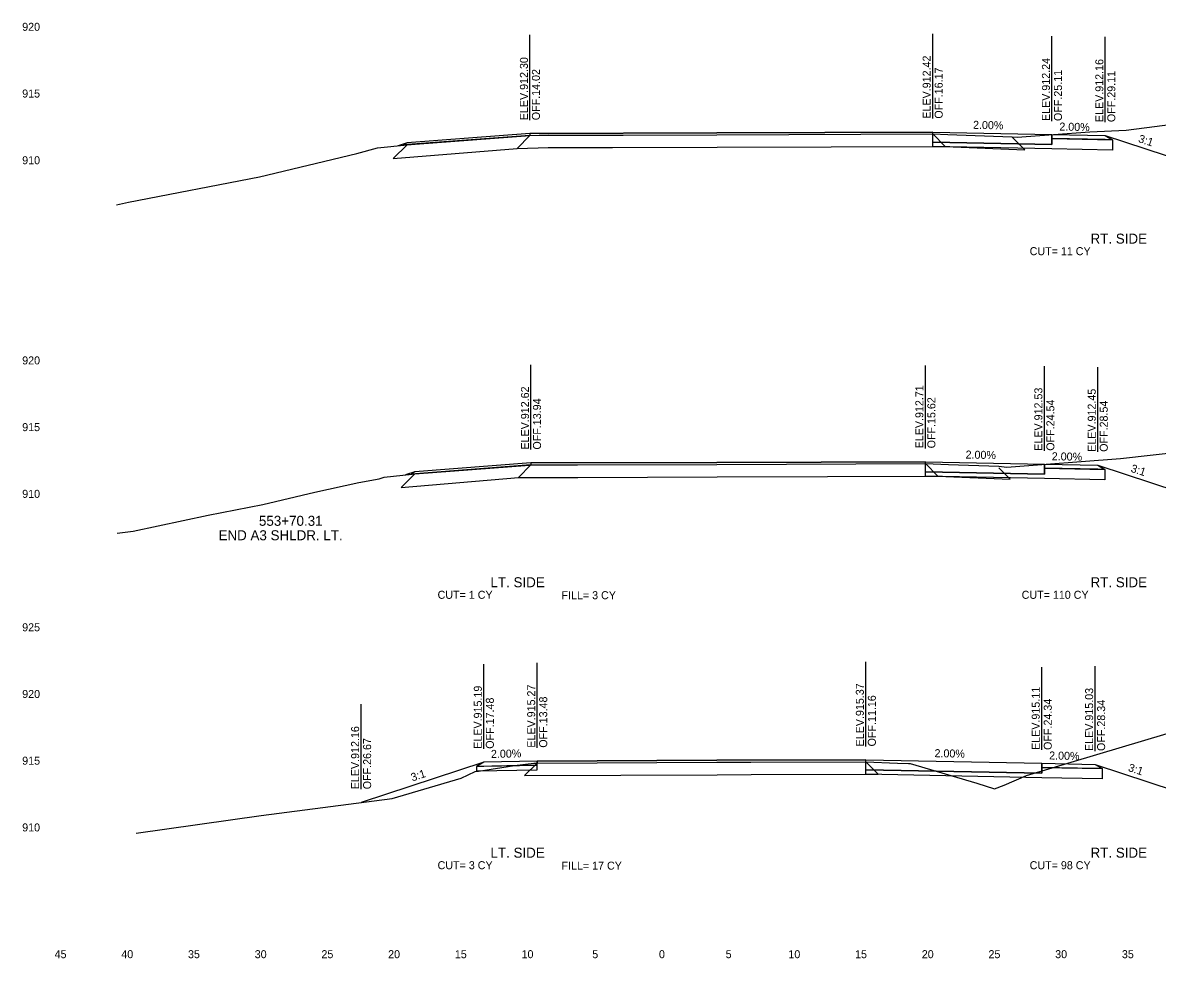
# Model space of a CAD drawing. Extents: x -4 to 359, y 0 to 1436.
# Drawn here: x 200.5 to 285.5, y 1200.5 to 1270.6 of the extents above; entities that cross this region are included whole.
import ezdxf

# ---------------------------------------------------------------- set-up
doc = ezdxf.new("R2010")
doc.units = 0
for name, color, linetype in [('XS-Existing subsurface-pavement', 7, 'Continuous'), ('XS-Existing subsurface-shoulder', 7, 'Continuous'), ('XS-Existing surface-ground', 7, 'Continuous'), ('XS-Proposed Finish Grade', 7, 'Continuous'), ('XS-Proposed subsurface-aggregate layer 1', 7, 'Continuous'), ('XS-Proposed surface-ground', 7, 'Continuous'), ('XS-Proposed surface-pavement', 7, 'Continuous'), ('XS-Proposed surface-shoulder', 7, 'Continuous'), ('XS-Text-ditch slope', 7, 'Continuous'), ('XS-Text-earthwork labels', 7, 'Continuous'), ('XS-Text-elevation', 7, 'Continuous'), ('XS-Text-offset label', 7, 'Continuous'), ('XS-Text-pavement elevation', 7, 'Continuous'), ('XS-Text-pavement slope', 7, 'Continuous'), ('XS-Text-profile report', 7, 'Continuous'), ('XS-Text-shoulder elevation', 7, 'Continuous'), ('XS-Text-shoulder slope', 7, 'Continuous'), ('XS-Text-tie elevation', 7, 'Continuous'), ('XS-Text-tie offset', 7, 'Continuous')]:
    doc.layers.add(name, color=color, linetype=linetype)

msp = doc.modelspace()

# ---------------------------------------------------------------- linework, layer by layer
at = {"layer": 'XS-Existing subsurface-pavement'}
for p, q in [((238.48, 1262.118), (237.512, 1261.15)), ((268.669, 1262.236), (269.603, 1261.301)), ((244.676, 1261.213), (252.503, 1261.241)), ((252.503, 1261.241), (269.603, 1261.301)), ((237.512, 1261.15), (239.871, 1261.224)), ((239.84, 1261.223), (244.67, 1261.213)), ((238.56, 1237.435), (237.622, 1236.498)), ((268.121, 1237.526), (269.055, 1236.592)), ((252.503, 1236.533), (269.055, 1236.592)), ((237.622, 1236.498), (242.058, 1236.496)), ((242.061, 1236.496), (252.503, 1236.533)), ((239.025, 1215.092), (238.083, 1214.151)), ((263.659, 1215.189), (264.593, 1214.254)), ((238.083, 1214.151), (252.504, 1214.212)), ((252.504, 1214.212), (255.054, 1214.223)), ((255.053, 1214.223), (264.593, 1214.254))]:
    msp.add_line(p, q, dxfattribs=at)
at = {"layer": 'XS-Existing subsurface-shoulder'}
for p, q in [((229.266, 1261.43), (228.234, 1260.398)), ((269.603, 1261.301), (275.584, 1261.054)), ((274.612, 1262.026), (275.584, 1261.054)), ((228.234, 1260.398), (237.512, 1261.15)), ((229.855, 1236.765), (228.837, 1235.748)), ((269.055, 1236.592), (274.476, 1236.364)), ((273.621, 1237.219), (274.476, 1236.364)), ((228.837, 1235.748), (237.622, 1236.498))]:
    msp.add_line(p, q, dxfattribs=at)
at = {"layer": 'XS-Existing surface-ground'}
for p, q in [((283.172, 1262.511), (291.485, 1263.596)), ((229.87, 1261.463), (238.48, 1262.118)), ((238.48, 1262.118), (239.842, 1262.161)), ((239.842, 1262.161), (244.672, 1262.151)), ((244.672, 1262.151), (252.5, 1262.178)), ((252.5, 1262.178), (268.669, 1262.236)), ((268.669, 1262.236), (269.807, 1262.195)), ((269.807, 1262.195), (274.612, 1262.026)), ((275.001, 1261.983), (280.453, 1262.398)), ((280.453, 1262.398), (283.172, 1262.511)), ((227.06, 1261.185), (229.266, 1261.43)), ((229.266, 1261.43), (229.87, 1261.463)), ((274.612, 1262.026), (275.001, 1261.983)), ((218.205, 1259.032), (225.508, 1260.772)), ((225.508, 1260.772), (227.06, 1261.185)), ((208.386, 1257.127), (218.205, 1259.032)), ((207.5, 1256.928), (208.386, 1257.127)), ((282.746, 1237.917), (310.956, 1241.132)), ((238.451, 1237.42), (238.56, 1237.435)), ((238.56, 1237.435), (242.058, 1237.434)), ((242.058, 1237.434), (252.5, 1237.471)), ((252.5, 1237.471), (268.121, 1237.526)), ((268.121, 1237.526), (269.849, 1237.464)), ((269.849, 1237.464), (273.621, 1237.332)), ((274.225, 1237.265), (282.746, 1237.917)), ((227.566, 1236.511), (229.659, 1236.737)), ((229.659, 1236.737), (229.855, 1236.765)), ((229.855, 1236.765), (238.451, 1237.42)), ((273.621, 1237.332), (274.225, 1237.265)), ((222.346, 1235.394), (225.651, 1236.113)), ((225.651, 1236.113), (227.182, 1236.394)), ((227.182, 1236.394), (227.566, 1236.511)), ((218.451, 1234.466), (222.346, 1235.394)), ((214.367, 1233.673), (218.451, 1234.466)), ((208.743, 1232.469), (214.367, 1233.673)), ((207.545, 1232.313), (208.743, 1232.469)), ((275.709, 1214.167), (286.257, 1217.301)), ((234.385, 1214.46), (234.62, 1214.491)), ((234.62, 1214.491), (237.325, 1214.894)), ((237.325, 1214.894), (238.766, 1215.09)), ((238.766, 1215.09), (239.025, 1215.092)), ((239.025, 1215.092), (252.5, 1215.15)), ((252.5, 1215.15), (255.05, 1215.161)), ((255.05, 1215.161), (263.659, 1215.189)), ((263.659, 1215.189), (266.037, 1215.084)), ((266.037, 1215.084), (266.852, 1215.049)), ((266.852, 1215.049), (266.978, 1215.047)), ((266.978, 1215.047), (271.973, 1213.579)), ((228.164, 1212.424), (233.338, 1213.965)), ((233.338, 1213.965), (234.385, 1214.46)), ((274.027, 1213.438), (275.709, 1214.167)), ((271.973, 1213.579), (273.313, 1213.154)), ((273.313, 1213.154), (274.027, 1213.438)), ((218.329, 1211.158), (228.164, 1212.424)), ((208.977, 1209.839), (218.329, 1211.158))]:
    msp.add_line(p, q, dxfattribs=at)
at = {"layer": 'XS-Proposed Finish Grade'}
for points in [[(238.48, 1262.264), (252.5, 1262.324), (268.669, 1262.381)], [(268.669, 1262.381), (277.609, 1262.203)], [(277.609, 1262.203), (281.609, 1262.123)], [(238.56, 1237.581), (252.5, 1237.617), (268.121, 1237.672)], [(268.121, 1237.672), (277.041, 1237.493)], [(277.041, 1237.493), (281.041, 1237.413)], [(239.025, 1215.238), (252.5, 1215.295), (263.659, 1215.335)], [(263.659, 1215.335), (276.844, 1215.071)], [(239.025, 1215.238), (235.025, 1215.158)], [(276.844, 1215.071), (280.844, 1214.991)]]:
    msp.add_lwpolyline(points, dxfattribs=at)
at = {"layer": 'XS-Proposed subsurface-aggregate layer 1'}
for points in [[(268.669, 1261.631), (277.609, 1261.453)], [(268.669, 1261.298), (268.669, 1261.631)], [(282.148, 1261.029), (277.609, 1261.119), (268.669, 1261.298)], [(277.609, 1261.453), (277.609, 1261.89)], [(277.609, 1261.89), (282.148, 1261.799)], [(282.148, 1261.799), (282.148, 1261.029)], [(268.121, 1236.922), (277.041, 1236.743)], [(268.121, 1236.589), (268.121, 1236.922)], [(281.58, 1236.319), (277.041, 1236.41), (268.121, 1236.589)], [(277.041, 1236.743), (277.041, 1237.181)], [(277.041, 1237.181), (281.58, 1237.09)], [(281.58, 1237.09), (281.58, 1236.319)], [(239.025, 1214.926), (234.486, 1214.835)], [(234.486, 1214.835), (234.486, 1214.502)], [(234.486, 1214.502), (239.025, 1214.592)], [(239.025, 1214.592), (239.025, 1214.926)], [(263.659, 1214.585), (276.844, 1214.321)], [(263.659, 1214.251), (263.659, 1214.585)], [(276.844, 1214.321), (276.844, 1214.758)], [(276.844, 1214.758), (281.382, 1214.668)], [(281.382, 1214.668), (281.382, 1213.897)], [(281.382, 1213.897), (276.844, 1213.988), (263.659, 1214.251)]]:
    msp.add_lwpolyline(points, dxfattribs=at)
at = {"layer": 'XS-Proposed surface-ground'}
for points in [[(281.609, 1262.123), (287.609, 1260.143), (291.609, 1260.143), (300.591, 1264.634)], [(229.266, 1261.576), (228.6, 1261.356)], [(281.041, 1237.413), (287.041, 1235.433), (291.041, 1235.433), (299.923, 1239.874)], [(229.855, 1236.912), (229.163, 1236.683)], [(280.844, 1214.991), (286.844, 1213.011), (290.844, 1213.011), (301.206, 1218.192)], [(235.025, 1215.158), (225.827, 1212.123)]]:
    msp.add_lwpolyline(points, dxfattribs=at)
at = {"layer": 'XS-Proposed surface-pavement'}
for points in [[(268.669, 1262.381), (252.5, 1262.324), (238.48, 1262.264)], [(238.48, 1262.264), (238.48, 1262.118)], [(238.48, 1262.118), (252.5, 1262.178), (268.669, 1262.236)], [(268.669, 1262.381), (277.609, 1262.203)], [(268.669, 1261.631), (268.669, 1262.381)], [(268.669, 1262.236), (268.669, 1262.381)], [(277.609, 1262.203), (277.609, 1261.453)], [(277.609, 1261.453), (268.669, 1261.631)], [(268.121, 1237.672), (252.5, 1237.617), (238.56, 1237.581)], [(238.56, 1237.581), (238.56, 1237.435)], [(238.56, 1237.435), (252.5, 1237.471), (268.121, 1237.526)], [(268.121, 1237.672), (277.041, 1237.493)], [(268.121, 1236.922), (268.121, 1237.672)], [(268.121, 1237.526), (268.121, 1237.672)], [(277.041, 1237.493), (277.041, 1236.743)], [(277.041, 1236.743), (268.121, 1236.922)], [(263.659, 1215.335), (252.5, 1215.295), (239.025, 1215.238)], [(263.659, 1215.335), (276.844, 1215.071)], [(263.659, 1214.585), (263.659, 1215.335)], [(263.659, 1215.189), (263.659, 1215.335)], [(239.025, 1215.238), (239.025, 1215.092)], [(239.025, 1215.092), (252.5, 1215.15), (263.659, 1215.189)], [(276.844, 1214.321), (263.659, 1214.585)], [(276.844, 1215.071), (276.844, 1214.321)]]:
    msp.add_lwpolyline(points, dxfattribs=at)
at = {"layer": 'XS-Proposed surface-shoulder'}
for p, q in [((238.48, 1262.118), (228.989, 1261.41)), ((238.48, 1262.264), (229.266, 1261.576)), ((229.266, 1261.576), (228.989, 1261.41)), ((238.56, 1237.435), (229.576, 1236.744)), ((238.56, 1237.581), (229.855, 1236.912)), ((229.855, 1236.912), (229.576, 1236.744))]:
    msp.add_line(p, q, dxfattribs=at)
for points in [[(277.609, 1262.203), (281.609, 1262.123), (282.148, 1261.799)], [(277.609, 1261.89), (277.609, 1262.203)], [(282.148, 1261.799), (281.609, 1261.81), (277.609, 1261.89)], [(277.041, 1237.493), (281.041, 1237.413), (281.58, 1237.09)], [(277.041, 1237.181), (277.041, 1237.493)], [(281.58, 1237.09), (281.041, 1237.101), (277.041, 1237.181)], [(239.025, 1215.238), (235.025, 1215.158), (234.486, 1214.835)], [(234.486, 1214.835), (235.025, 1214.846), (239.025, 1214.926)], [(239.025, 1214.926), (239.025, 1215.238)], [(276.844, 1215.071), (280.844, 1214.991), (281.382, 1214.668)], [(276.844, 1214.758), (276.844, 1215.071)], [(281.382, 1214.668), (280.844, 1214.678), (276.844, 1214.758)]]:
    msp.add_lwpolyline(points, dxfattribs=at)
at = {"layer": 'XS-Text-tie offset'}
for p, q in [((238.48, 1263.264), (238.48, 1269.662)), ((268.669, 1263.381), (268.669, 1269.731)), ((277.609, 1263.203), (277.609, 1269.553)), ((281.609, 1263.123), (281.609, 1269.501)), ((238.56, 1238.581), (238.56, 1244.931)), ((268.121, 1238.672), (268.121, 1244.872)), ((277.041, 1238.493), (277.041, 1244.843)), ((281.041, 1238.413), (281.041, 1244.765)), ((235.025, 1216.158), (235.025, 1222.508)), ((239.025, 1216.238), (239.025, 1222.588)), ((263.659, 1216.335), (263.659, 1222.684)), ((276.844, 1216.071), (276.844, 1222.271)), ((280.844, 1215.991), (280.844, 1222.341)), ((225.827, 1213.123), (225.827, 1219.501))]:
    msp.add_line(p, q, dxfattribs=at)

# ---------------------------------------------------------------- texts
at = {"layer": 'XS-Text-ditch slope'}
for rotation, p in [(341.73711, (284.038, 1261.637)), (341.73711, (283.471, 1236.928)), (18.26289, (229.667, 1213.706)), (341.73711, (283.273, 1214.505))]:
    msp.add_text('3:1', height=0.6, rotation=rotation, dxfattribs=at).set_placement(p)
at = {"layer": 'XS-Text-earthwork labels'}
for s, height, p in [('RT. SIDE', 0.75, (280.501, 1254.015)), (' CUT= 11 CY           ', 0.6, (275.715, 1253.15)), ('553+70.31', 0.75, (218.169, 1232.867)), ('END A3 SHLDR. LT.', 0.75, (215.139, 1231.785)), ('LT. SIDE', 0.75, (235.522, 1228.263)), ('RT. SIDE', 0.75, (280.501, 1228.263)), (' CUT= 1 CY           ', 0.6, (231.335, 1227.398)), ('FILL= 3 CY           ', 0.6, (240.846, 1227.366)), (' CUT= 110 CY           ', 0.6, (275.115, 1227.398)), ('LT. SIDE', 0.75, (235.522, 1207.996)), ('RT. SIDE', 0.75, (280.501, 1207.996)), (' CUT= 3 CY           ', 0.6, (231.335, 1207.131)), ('FILL= 17 CY           ', 0.6, (240.846, 1207.099)), (' CUT= 98 CY           ', 0.6, (275.715, 1207.131))]:
    msp.add_text(s, height=height, dxfattribs=at).set_placement(p)
at = {"layer": 'XS-Text-elevation'}
for s, p in [('           920           ', (197.97, 1269.964)), ('           915           ', (197.97, 1264.964)), ('           910           ', (197.97, 1259.964)), ('           920           ', (197.97, 1244.964)), ('           915           ', (197.97, 1239.964)), ('           910           ', (197.97, 1234.964)), ('           925           ', (197.97, 1224.964)), ('           920           ', (197.97, 1219.964)), ('           915           ', (197.97, 1214.964)), ('           910           ', (197.97, 1209.964))]:
    msp.add_text(s, height=0.6, dxfattribs=at).set_placement(p)
at = {"layer": 'XS-Text-offset label'}
for s, p in [('           45           ', (200.4, 1200.464)), ('           40           ', (205.4, 1200.464)), ('           35           ', (210.4, 1200.464)), ('           30           ', (215.4, 1200.464)), ('           25           ', (220.4, 1200.464)), ('           20           ', (225.4, 1200.464)), ('           15           ', (230.4, 1200.464)), ('           10           ', (235.4, 1200.464)), ('           5           ', (240.7, 1200.464)), ('           0           ', (245.7, 1200.464)), ('           0           ', (245.7, 1200.464)), ('           5           ', (250.7, 1200.464)), ('           10           ', (255.4, 1200.464)), ('           15           ', (260.4, 1200.464)), ('           20           ', (265.4, 1200.464)), ('           25           ', (270.4, 1200.464)), ('           30           ', (275.4, 1200.464)), ('           35           ', (280.4, 1200.464))]:
    msp.add_text(s, height=0.6, dxfattribs=at).set_placement(p)
at = {"layer": 'XS-Text-pavement elevation'}
for s, p in [('ELEV.912.42', (268.519, 1263.381)), ('ELEV.912.30', (238.33, 1263.264)), ('ELEV.912.24', (277.459, 1263.203)), ('OFF.14.02', (239.23, 1263.264)), ('OFF.16.17', (269.419, 1263.381)), ('OFF.25.11', (278.359, 1263.203)), ('ELEV.912.62', (238.41, 1238.581)), ('ELEV.912.71', (267.971, 1238.672)), ('ELEV.912.53', (276.891, 1238.493)), ('OFF.13.94', (239.31, 1238.581)), ('OFF.15.62', (268.871, 1238.672)), ('OFF.24.54', (277.791, 1238.493)), ('ELEV.915.19', (234.875, 1216.158)), ('ELEV.915.27', (238.875, 1216.238)), ('ELEV.915.37', (263.509, 1216.335)), ('ELEV.915.11', (276.694, 1216.071)), ('OFF.17.48', (235.775, 1216.158)), ('OFF.13.48', (239.775, 1216.238)), ('OFF.11.16', (264.409, 1216.335)), ('OFF.24.34', (277.594, 1216.071))]:
    msp.add_text(s, height=0.6, rotation=90, dxfattribs=at).set_placement(p)
at = {"layer": 'XS-Text-pavement slope'}
for p in [(271.689, 1262.621), (271.131, 1237.912), (268.801, 1215.532)]:
    msp.add_text('2.00%', height=0.6, rotation=358.85424, dxfattribs=at).set_placement(p)
at = {"layer": 'XS-Text-profile report'}
for s, p in [('Pvmt_Surf_Asph_T2_L', (238.464, 1262.263)), ('Pvmt_Surf_Asph_T_L', (238.465, 1262.118)), ('Pvmt_Surf_Asph_T1', (252.486, 1262.323)), ('Pvmt_Surf_Asph_T', (252.487, 1262.177)), ('Pvmt_Surf_Asph_T1_R', (268.653, 1262.381)), ('Pvmt_Surf_Asph_T_R', (268.654, 1262.235)), ('Pvmt_Surf_Conc_T1_R', (277.593, 1262.202)), ('Shldr_Surf_Asph_T11', (281.594, 1262.122)), ('Fill_Slope_2_B', (233.009, 1261.702)), ('Pvmt_Surf_Conc_B_R', (268.654, 1261.631)), ('Agg_Layer_1_B2', (268.657, 1261.297)), ('Shldr_Surf_Asph_B13', (277.593, 1261.889)), ('Pvmt_Surf_Conc_B1_R', (277.593, 1261.452)), ('Shldr_Surf_Asph_B11', (281.594, 1261.809)), ('Shldr_Surf_Asph_B21', (282.132, 1261.798)), ('Agg_Layer_1_B11', (277.597, 1261.118)), ('Agg_Layer_1_B12', (282.135, 1261.028)), ('Rt_Agg_Layer_1_B13', (285.089, 1260.969)), ('Pvmt_Surf_Asph_T2_L', (238.544, 1237.58)), ('Pvmt_Surf_Asph_T_L', (238.545, 1237.434)), ('Pvmt_Surf_Asph_T1', (252.486, 1237.616)), ('Pvmt_Surf_Asph_T', (252.487, 1237.47)), ('Pvmt_Surf_Asph_T1_R', (268.105, 1237.671)), ('Pvmt_Surf_Asph_T_R', (268.106, 1237.525)), ('Pvmt_Surf_Conc_T1_R', (277.026, 1237.493)), ('Pvmt_Surf_Conc_B_R', (268.106, 1236.921)), ('Agg_Layer_1_B2', (268.109, 1236.588)), ('Shldr_Surf_Asph_B13', (277.026, 1237.18)), ('Pvmt_Surf_Conc_B1_R', (277.026, 1236.743)), ('Shldr_Surf_Asph_T11', (281.026, 1237.413)), ('Shldr_Surf_Asph_B11', (281.026, 1237.1)), ('Shldr_Surf_Asph_B21', (281.565, 1237.089)), ('Agg_Layer_1_B11', (277.029, 1236.409)), ('Agg_Layer_1_B12', (281.568, 1236.319)), ('Rt_Agg_Layer_1_B13', (284.521, 1236.259)), ('Pvmt_Surf_Asph_T1_R', (263.643, 1215.334)), ('Shldr_Surf_Asph_B2', (234.471, 1214.834)), ('Agg_Layer_1_B1', (234.475, 1214.501)), ('Shldr_Surf_Asph_T1', (235.01, 1215.157)), ('Shldr_Surf_Asph_B1', (235.01, 1214.845)), ('Pvmt_Surf_Asph_T2_L', (239.009, 1215.237)), ('Shldr_Surf_Asph_B12', (239.009, 1214.925)), ('Pvmt_Surf_Asph_T_L', (239.01, 1215.092)), ('Agg_Layer_1_B', (239.014, 1214.592)), ('Pvmt_Surf_Asph_T1', (252.486, 1215.294)), ('Pvmt_Surf_Asph_T', (252.487, 1215.149)), ('Pvmt_Surf_Asph_T_R', (263.644, 1215.188)), ('Pvmt_Surf_Conc_B_R', (263.644, 1214.584)), ('Pvmt_Surf_Conc_T1_R', (276.828, 1215.07)), ('Shldr_Surf_Asph_B13', (276.828, 1214.757)), ('Shldr_Surf_Asph_T11', (280.828, 1214.99)), ('Shldr_Surf_Asph_B11', (280.828, 1214.677)), ('Shldr_Surf_Asph_B21', (281.367, 1214.667)), ('Agg_Layer_1_B2', (263.647, 1214.25)), ('Pvmt_Surf_Conc_B1_R', (276.828, 1214.32)), ('Agg_Layer_1_B11', (276.832, 1213.987)), ('Agg_Layer_1_B12', (281.37, 1213.896)), ('Rt_Agg_Layer_1_B13', (284.324, 1213.837)), ('Fill_Slope_2_B', (225.816, 1212.122))]:
    msp.add_text(s, height=0.00167, dxfattribs=at).set_placement(p)
at = {"layer": 'XS-Text-shoulder elevation'}
for s, p in [('ELEV.912.16', (281.459, 1263.123)), ('OFF.29.11', (282.359, 1263.123)), ('ELEV.912.45', (280.891, 1238.413)), ('OFF.28.54', (281.791, 1238.413)), ('ELEV.915.03', (280.694, 1215.991)), ('OFF.28.34', (281.594, 1215.991))]:
    msp.add_text(s, height=0.6, rotation=90, dxfattribs=at).set_placement(p)
at = {"layer": 'XS-Text-shoulder slope'}
for rotation, p in [(358.85424, (278.159, 1262.492)), (358.85424, (277.591, 1237.783)), (1.14576, (235.563, 1215.469)), (358.85424, (277.394, 1215.36))]:
    msp.add_text('2.00%', height=0.6, rotation=rotation, dxfattribs=at).set_placement(p)
at = {"layer": 'XS-Text-tie elevation'}
for s, p in [('ELEV.912.16', (225.677, 1213.123)), ('OFF.26.67', (226.577, 1213.123))]:
    msp.add_text(s, height=0.6, rotation=90, dxfattribs=at).set_placement(p)

doc.saveas('drawing.dxf')
